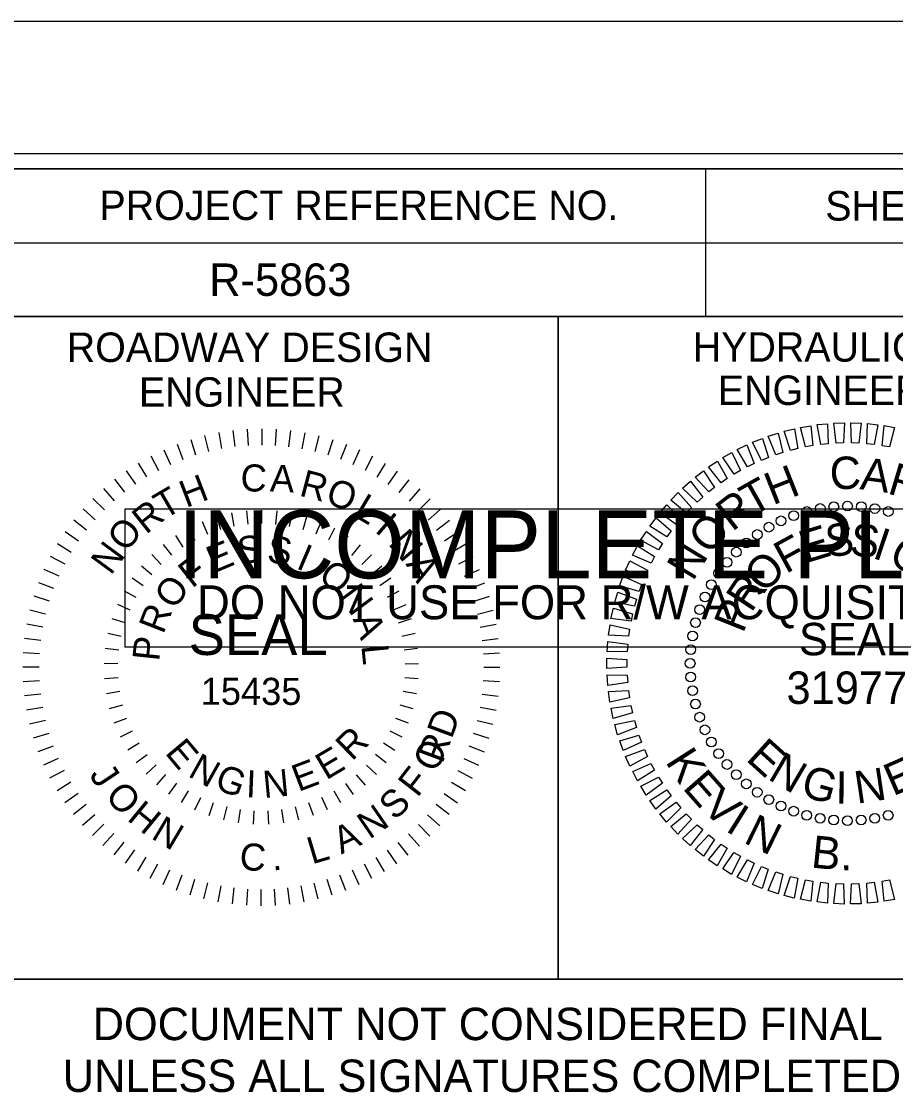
# Model space of a CAD drawing. Extents: x 557032 to 562069, y 513430 to 515874.
# Drawn here: x 558508.4 to 558656.7, y 515691.5 to 515874.3 of the extents above; entities that cross this region are included whole.
import ezdxf

# ---------------------------------------------------------------- set-up
doc = ezdxf.new("R2010")
doc.units = 0
for name, color, linetype in [('Default', 7, 'Continuous'), ('Old_Level_21', 7, 'Continuous'), ('Sheet Cutting Line CELL', 7, 'Continuous'), ('Sheet Data Field CELL', 7, 'Continuous'), ('Sheet Plot Border Inside CELL', 7, 'Continuous'), ('Sheet Plot Border Outside CELL', 7, 'Continuous'), ('Sheet Profile CELL', 7, 'Continuous'), ('Sheet Profile Grid Major CELL', 7, 'Continuous'), ('Sheet Sticker Exception Certification CELL', 7, 'Continuous'), ('Sheet Sticker Incomplete CELL', 7, 'Continuous')]:
    doc.layers.add(name, color=color, linetype=linetype)

msp = doc.modelspace()

# ---------------------------------------------------------------- linework, layer by layer
at = {"layer": 'Default'}
for points in [[(558644.01, 515802.48), (558643.39, 515805.86), (558645.17, 515806.01), (558645.26, 515802.62)], [(558646.61, 515802.7), (558646.23, 515806.12), (558648.01, 515806.15), (558647.87, 515802.76)], [(558649.23, 515802.75), (558649.08, 515806.18), (558650.86, 515806.09), (558650.48, 515802.71)], [(558651.83, 515802.61), (558651.93, 515806.04), (558653.7, 515805.82), (558653.08, 515802.49)], [(558636.39, 515800.73), (558635.08, 515803.9), (558636.78, 515804.42), (558637.58, 515801.12)], [(558638.89, 515801.49), (558637.8, 515804.75), (558639.54, 515805.15), (558640.1, 515801.8)], [(558641.43, 515802.07), (558640.58, 515805.4), (558642.34, 515805.68), (558642.67, 515802.3)], [(558654.43, 515802.29), (558654.76, 515805.71), (558656.51, 515805.37), (558655.67, 515802.08)], [(558631.58, 515798.69), (558629.84, 515801.66), (558631.46, 515802.41), (558632.71, 515799.25)], [(558633.95, 515799.79), (558632.42, 515802.87), (558634.09, 515803.51), (558635.11, 515800.27)], [(558629.29, 515797.43), (558627.36, 515800.26), (558628.91, 515801.12), (558630.38, 515798.06)], [(558627.1, 515796.01), (558624.97, 515798.7), (558626.46, 515799.67), (558628.14, 515796.72)], [(558625.02, 515794.44), (558622.7, 515796.97), (558624.12, 515798.04), (558626, 515795.22)], [(558623.04, 515792.72), (558620.56, 515795.1), (558621.9, 515796.26), (558623.97, 515793.57)], [(558621.19, 515790.88), (558618.55, 515793.07), (558619.81, 515794.33), (558622.06, 515791.79)], [(558619.48, 515788.91), (558616.69, 515790.91), (558617.86, 515792.25), (558620.28, 515789.88)], [(558617.91, 515786.82), (558614.98, 515788.63), (558616.05, 515790.05), (558618.64, 515787.85)], [(558616.48, 515784.64), (558613.44, 515786.23), (558614.41, 515787.72), (558617.14, 515785.71)], [(558615.21, 515782.35), (558612.07, 515783.73), (558612.93, 515785.29), (558615.8, 515783.47)], [(558614.11, 515779.99), (558610.87, 515781.14), (558611.62, 515782.75), (558614.61, 515781.14)], [(558613.17, 515777.55), (558609.86, 515778.48), (558610.5, 515780.14), (558613.59, 515778.73)], [(558612.4, 515775.05), (558609.04, 515775.75), (558609.56, 515777.45), (558612.74, 515776.26)], [(558611.81, 515772.51), (558608.41, 515772.96), (558608.81, 515774.7), (558612.07, 515773.74)], [(558611.4, 515769.93), (558607.97, 515770.15), (558608.25, 515771.9), (558611.57, 515771.17)], [(558611.17, 515767.33), (558607.74, 515767.31), (558607.89, 515769.08), (558611.25, 515768.58)], [(558611.12, 515764.71), (558607.7, 515764.45), (558607.73, 515766.23), (558611.12, 515765.97)], [(558611.26, 515762.11), (558607.86, 515761.61), (558607.77, 515763.38), (558611.16, 515763.36)], [(558611.58, 515759.51), (558608.22, 515758.78), (558608, 515760.55), (558611.39, 515760.76)], [(558612.07, 515756.95), (558608.77, 515755.98), (558608.44, 515757.73), (558611.8, 515758.18)], [(558612.75, 515754.43), (558609.52, 515753.23), (558609.06, 515754.95), (558612.39, 515755.63)], [(558613.59, 515751.96), (558610.46, 515750.54), (558609.89, 515752.22), (558613.16, 515753.13)], [(558614.61, 515749.55), (558611.59, 515747.92), (558610.89, 515749.56), (558614.09, 515750.7)], [(558615.8, 515747.22), (558612.89, 515745.38), (558612.09, 515746.97), (558615.2, 515748.33)], [(558617.14, 515744.98), (558614.37, 515742.95), (558613.46, 515744.47), (558616.47, 515746.04)], [(558618.64, 515742.84), (558616.02, 515740.62), (558615, 515742.08), (558617.89, 515743.85)], [(558620.28, 515740.81), (558617.82, 515738.41), (558616.7, 515739.79), (558619.46, 515741.77)], [(558622.06, 515738.9), (558619.77, 515736.33), (558618.56, 515737.63), (558621.18, 515739.8)], [(558623.97, 515737.12), (558621.87, 515734.4), (558620.57, 515735.61), (558623.03, 515737.95)], [(558625.99, 515735.47), (558624.09, 515732.61), (558622.71, 515733.73), (558625, 515736.24)], [(558628.13, 515733.97), (558626.43, 515730.98), (558624.97, 515732.01), (558627.08, 515734.67)], [(558630.37, 515732.62), (558628.88, 515729.53), (558627.36, 515730.44), (558629.28, 515733.24)], [(558632.7, 515731.43), (558631.43, 515728.24), (558629.84, 515729.05), (558631.56, 515731.98)], [(558635.1, 515730.41), (558634.06, 515727.14), (558632.42, 515727.83), (558633.93, 515730.88)], [(558637.57, 515729.56), (558636.76, 515726.22), (558635.07, 515726.8), (558636.37, 515729.94)], [(558640.09, 515728.88), (558639.51, 515725.49), (558637.79, 515725.96), (558638.87, 515729.18)], [(558642.65, 515728.38), (558642.31, 515724.96), (558640.57, 515725.3), (558641.41, 515728.59)], [(558645.25, 515728.06), (558645.15, 515724.63), (558643.38, 515724.84), (558643.99, 515728.18)], [(558647.85, 515727.92), (558647.99, 515724.49), (558646.22, 515724.58), (558646.6, 515727.96)], [(558650.46, 515727.96), (558650.84, 515724.55), (558649.07, 515724.52), (558649.21, 515727.91)], [(558653.07, 515728.19), (558653.68, 515724.81), (558651.91, 515724.66), (558651.82, 515728.05)], [(558655.65, 515728.6), (558656.5, 515725.27), (558654.74, 515724.99), (558654.41, 515728.37)]]:
    msp.add_lwpolyline(points, close=True, dxfattribs=at)
for centre in [(558639.41, 515790.42), (558641.63, 515791.12), (558643.91, 515791.63), (558646.22, 515791.93), (558648.54, 515792.03), (558650.87, 515791.93), (558653.18, 515791.62), (558655.45, 515791.12), (558635.2, 515788.46), (558637.26, 515789.53), (558633.23, 515787.21), (558631.38, 515785.79), (558629.67, 515784.22), (558628.09, 515782.5), (558626.67, 515780.65), (558625.42, 515778.69), (558624.35, 515776.62), (558623.45, 515774.47), (558622.75, 515772.25), (558622.25, 515769.98), (558621.95, 515767.67), (558621.84, 515765.34), (558621.94, 515763.01), (558622.25, 515760.7), (558622.75, 515758.43), (558623.45, 515756.21), (558624.34, 515754.06), (558625.42, 515751.99), (558626.67, 515750.03), (558628.09, 515748.18), (558629.66, 515746.46), (558631.38, 515744.89), (558633.22, 515743.47), (558635.19, 515742.22), (558637.25, 515741.14), (558639.4, 515740.25), (558641.62, 515739.55), (558655.44, 515739.55), (558643.9, 515739.04), (558646.21, 515738.74), (558648.53, 515738.64), (558650.86, 515738.74), (558653.17, 515739.04)]:
    msp.add_circle(centre, 0.826, dxfattribs=at)
at = {"layer": 'Old_Level_21'}
for p, q in [((558539.47, 515804), (558540.12, 515801.32)), ((558541.86, 515804.51), (558542.35, 515801.79)), ((558544.28, 515804.87), (558544.6, 515802.13)), ((558546.71, 515805.09), (558546.87, 515802.33)), ((558549.16, 515805.16), (558549.15, 515802.4)), ((558551.6, 515805.08), (558551.43, 515802.33)), ((558554.04, 515804.86), (558553.7, 515802.12)), ((558556.45, 515804.49), (558555.95, 515801.77)), ((558558.84, 515803.97), (558558.18, 515801.29)), ((558534.8, 515802.55), (558535.78, 515799.97)), ((558537.11, 515803.35), (558537.93, 515800.71)), ((558561.2, 515803.31), (558560.38, 515800.67)), ((558563.51, 515802.51), (558562.52, 515799.93)), ((558530.34, 515800.55), (558531.62, 515798.1)), ((558532.54, 515801.61), (558533.67, 515799.1)), ((558565.76, 515801.57), (558564.63, 515799.06)), ((558567.96, 515800.5), (558566.68, 515798.05)), ((558528.21, 515799.35), (558529.63, 515796.99)), ((558570.09, 515799.29), (558568.66, 515796.93)), ((558524.18, 515796.58), (558525.88, 515794.41)), ((558526.15, 515798.03), (558527.72, 515795.75)), ((558572.14, 515797.96), (558570.57, 515795.69)), ((558522.3, 515795.02), (558524.13, 515792.95)), ((558574.11, 515796.51), (558572.41, 515794.34)), ((558575.99, 515794.94), (558574.15, 515792.88)), ((558520.52, 515793.34), (558522.47, 515791.39)), ((558577.76, 515793.26), (558575.81, 515791.32)), ((558518.84, 515791.57), (558520.9, 515789.73)), ((558546.56, 515791.24), (558546.78, 515788.95)), ((558549.14, 515791.36), (558549.14, 515789.06)), ((558549.14, 515789.06), (558549.14, 515791.36)), ((558551.72, 515791.23), (558551.49, 515788.94)), ((558579.44, 515791.48), (558577.37, 515789.65)), ((558517.27, 515789.69), (558519.44, 515787.99)), ((558539.07, 515789.41), (558539.94, 515787.27)), ((558541.51, 515790.26), (558542.16, 515788.05)), ((558544.01, 515790.87), (558544.45, 515788.61)), ((558554.26, 515790.85), (558553.82, 515788.6)), ((558556.76, 515790.24), (558556.11, 515788.03)), ((558559.2, 515789.38), (558558.33, 515787.25)), ((558581, 515789.6), (558578.83, 515787.9)), ((558515.82, 515787.72), (558518.09, 515786.15)), ((558536.74, 515788.32), (558537.8, 515786.28)), ((558561.53, 515788.29), (558560.46, 515786.25)), ((558582.45, 515787.63), (558580.18, 515786.06)), ((558514.49, 515785.67), (558516.85, 515784.24)), ((558534.51, 515787.02), (558535.77, 515785.09)), ((558563.75, 515786.98), (558562.49, 515785.05)), ((558530.49, 515783.8), (558532.1, 515782.15)), ((558532.42, 515785.5), (558533.86, 515783.71)), ((558565.84, 515785.46), (558564.39, 515783.66)), ((558583.77, 515785.58), (558581.41, 515784.15)), ((558513.28, 515783.54), (558515.73, 515782.26)), ((558567.76, 515783.75), (558566.15, 515782.1)), ((558584.97, 515783.44), (558582.53, 515782.16)), ((558512.21, 515781.34), (558514.73, 515780.21)), ((558528.74, 515781.91), (558530.49, 515780.43)), ((558569.52, 515781.86), (558567.76, 515780.38)), ((558586.04, 515781.24), (558583.52, 515780.11)), ((558511.27, 515779.09), (558513.85, 515778.1)), ((558527.16, 515779.87), (558529.06, 515778.55)), ((558571.08, 515779.81), (558569.19, 515778.5)), ((558586.97, 515778.98), (558584.39, 515778)), ((558510.47, 515776.78), (558513.11, 515775.95)), ((558525.81, 515777.68), (558527.81, 515776.56)), ((558572.43, 515777.62), (558570.43, 515776.5)), ((558587.77, 515776.67), (558585.13, 515775.85)), ((558524.66, 515775.37), (558526.76, 515774.45)), ((558573.58, 515775.3), (558571.47, 515774.39)), ((558509.81, 515774.42), (558512.49, 515773.76)), ((558523.74, 515772.96), (558525.93, 515772.25)), ((558574.49, 515772.89), (558572.3, 515772.18)), ((558588.42, 515774.31), (558585.74, 515773.66)), ((558509.29, 515772.03), (558512.01, 515771.53)), ((558588.93, 515771.92), (558586.22, 515771.43)), ((558508.93, 515769.62), (558511.66, 515769.28)), ((558523.06, 515770.47), (558525.3, 515769.97)), ((558575.16, 515770.4), (558572.91, 515769.91)), ((558589.29, 515769.5), (558586.55, 515769.18)), ((558522.62, 515767.93), (558524.9, 515767.66)), ((558575.59, 515767.86), (558573.31, 515767.59)), ((558508.7, 515767.18), (558511.45, 515767.01)), ((558589.51, 515767.07), (558586.76, 515766.91)), ((558508.62, 515764.74), (558511.38, 515764.73)), ((558522.43, 515765.36), (558524.73, 515765.3)), ((558575.78, 515765.29), (558573.48, 515765.23)), ((558589.58, 515764.62), (558586.82, 515764.63)), ((558508.69, 515762.29), (558511.45, 515762.45)), ((558522.49, 515762.78), (558524.78, 515762.95)), ((558575.71, 515762.71), (558573.42, 515762.88)), ((558589.5, 515762.18), (558586.75, 515762.35)), ((558508.91, 515759.86), (558511.65, 515760.18)), ((558522.8, 515760.23), (558525.06, 515760.61)), ((558573.14, 515760.62), (558575.41, 515760.24)), ((558589.28, 515759.74), (558586.54, 515760.08)), ((558523.35, 515757.7), (558525.57, 515758.31)), ((558574.84, 515757.63), (558572.62, 515758.24)), ((558509.27, 515757.44), (558511.99, 515757.93)), ((558588.91, 515757.33), (558586.2, 515757.83)), ((558509.78, 515755.05), (558512.46, 515755.7)), ((558524.14, 515755.25), (558526.29, 515756.06)), ((558574.03, 515755.18), (558571.89, 515756)), ((558588.39, 515754.94), (558585.71, 515755.6)), ((558510.44, 515752.69), (558513.08, 515753.51)), ((558525.17, 515752.89), (558527.23, 515753.91)), ((558573, 515752.82), (558570.94, 515753.85)), ((558587.73, 515752.58), (558585.1, 515753.41)), ((558511.23, 515750.38), (558513.81, 515751.36)), ((558526.42, 515750.64), (558528.37, 515751.84)), ((558571.75, 515750.57), (558569.79, 515751.79)), ((558586.93, 515750.27), (558584.35, 515751.26)), ((558512.17, 515748.12), (558514.68, 515749.25)), ((558527.88, 515748.51), (558529.71, 515749.9)), ((558570.28, 515748.45), (558568.45, 515749.85)), ((558585.99, 515748.02), (558583.48, 515749.15)), ((558529.54, 515746.54), (558531.22, 515748.1)), ((558568.61, 515746.49), (558566.93, 515748.05)), ((558513.23, 515745.92), (558515.68, 515747.2)), ((558531.38, 515744.74), (558532.91, 515746.46)), ((558566.77, 515744.69), (558565.24, 515746.41)), ((558584.92, 515745.82), (558582.48, 515747.1)), ((558514.43, 515743.79), (558516.79, 515745.21)), ((558533.39, 515743.12), (558534.74, 515744.98)), ((558535.54, 515741.7), (558536.71, 515743.69)), ((558562.6, 515741.67), (558561.43, 515743.65)), ((558564.75, 515743.08), (558563.41, 515744.94)), ((558583.71, 515743.69), (558581.36, 515745.12)), ((558515.76, 515741.73), (558518.03, 515743.3)), ((558537.83, 515740.5), (558538.8, 515742.59)), ((558560.31, 515740.47), (558559.34, 515742.56)), ((558582.38, 515741.64), (558580.12, 515743.21)), ((558517.2, 515739.76), (558519.38, 515741.46)), ((558540.21, 515739.53), (558540.98, 515741.7)), ((558543.22, 515741.02), (558542.66, 515738.79)), ((558545.21, 515738.29), (558545.55, 515740.56)), ((558547.78, 515738.03), (558547.89, 515740.33)), ((558550.35, 515738.03), (558550.25, 515740.33)), ((558552.92, 515738.28), (558552.59, 515740.55)), ((558555.45, 515738.77), (558554.9, 515741)), ((558557.92, 515739.5), (558557.16, 515741.67)), ((558580.93, 515739.67), (558578.76, 515741.38)), ((558518.77, 515737.88), (558520.83, 515739.71)), ((558579.36, 515737.79), (558577.3, 515739.63)), ((558520.44, 515736.1), (558522.39, 515738.04)), ((558522.22, 515734.42), (558524.05, 515736.48)), ((558575.9, 515734.34), (558574.08, 515736.41)), ((558577.68, 515736.02), (558575.74, 515737.97)), ((558524.1, 515732.85), (558525.8, 515735.02)), ((558574.02, 515732.78), (558572.32, 515734.95)), ((558526.06, 515731.4), (558527.63, 515733.67)), ((558572.05, 515731.33), (558570.49, 515733.61)), ((558528.11, 515730.07), (558529.54, 515732.43)), ((558530.24, 515728.86), (558531.53, 515731.31)), ((558567.86, 515728.81), (558566.58, 515731.26)), ((558570, 515730.01), (558568.57, 515732.37)), ((558532.44, 515727.79), (558533.57, 515730.31)), ((558534.7, 515726.85), (558535.68, 515729.43)), ((558563.4, 515726.81), (558562.43, 515729.39)), ((558565.66, 515727.75), (558564.54, 515730.26)), ((558537, 515726.05), (558537.83, 515728.69)), ((558539.36, 515725.39), (558540.02, 515728.07)), ((558541.75, 515724.87), (558542.25, 515727.59)), ((558544.17, 515724.5), (558544.5, 515727.24)), ((558553.93, 515724.49), (558553.6, 515727.23)), ((558556.34, 515724.85), (558555.85, 515727.57)), ((558558.73, 515725.36), (558558.08, 515728.04)), ((558561.09, 515726.01), (558560.28, 515728.65)), ((558546.6, 515724.28), (558546.77, 515727.03)), ((558549.05, 515724.2), (558549.05, 515726.96)), ((558551.49, 515724.27), (558551.33, 515727.03))]:
    msp.add_line(p, q, dxfattribs=at)
at = {"layer": 'Sheet Cutting Line CELL'}
msp.add_line((558716.45, 515874.28), (557032.45, 515874.28), dxfattribs=at)
at = {"layer": 'Sheet Plot Border Inside CELL'}
msp.add_lwpolyline([(557045.45, 514796.73), (558711.95, 514796.73), (558711.95, 515851.83), (557045.45, 515851.83)], close=True, dxfattribs=at)
at = {"layer": 'Sheet Plot Border Outside CELL'}
msp.add_lwpolyline([(557032.45, 514774.28), (558716.45, 514774.28), (558716.45, 515874.28), (557032.45, 515874.28)], close=True, dxfattribs=at)
at = {"layer": 'Sheet Profile CELL'}
for p, q in [((558624.45, 515849.23), (558624.45, 515824.23)), ((558499.4, 515836.73), (558699.45, 515836.73)), ((558599.45, 515824.23), (558599.45, 515711.78))]:
    msp.add_line(p, q, dxfattribs=at)
for points in [[(558699.45, 515849.28), (557199.45, 515849.28), (557199.45, 514799.28), (558699.45, 514799.28)], [(558499.4, 515849.28), (558699.45, 515849.28), (558699.45, 515824.23), (558499.4, 515824.23)], [(558499.4, 515824.23), (558599.45, 515824.23), (558599.45, 515711.73), (558499.4, 515711.73)], [(558599.45, 515824.23), (558699.45, 515824.23), (558699.45, 515711.73), (558599.45, 515711.73)]]:
    msp.add_lwpolyline(points, close=True, dxfattribs=at)
at = {"layer": 'Sheet Profile Grid Major CELL'}
msp.add_lwpolyline([(558149.45, 515349.28), (558199.45, 515349.28), (558199.45, 515849.28), (558249.45, 515849.28), (558249.45, 515349.28), (558299.45, 515349.28), (558299.45, 515849.28), (558349.45, 515849.28), (558349.45, 515349.28), (558399.45, 515349.28), (558399.45, 515849.28), (558449.45, 515849.28), (558449.45, 515349.28), (558499.45, 515349.28), (558499.45, 515849.28), (558525.75, 515849.28)], dxfattribs=at)
at = {"layer": 'Sheet Sticker Exception Certification CELL'}
msp.add_line((558499.4, 515711.73), (558699.44, 515711.73), dxfattribs=at)
msp.add_line((558499.4, 515711.73), (558699.44, 515711.73), dxfattribs=at)
at = {"layer": 'Sheet Sticker Incomplete CELL'}
msp.add_lwpolyline([(558525.97, 515768.08), (558525.97, 515791.58), (558672.97, 515791.58), (558672.97, 515768.08)], close=True, dxfattribs=at)

# ---------------------------------------------------------------- texts
at = {"layer": 'Default'}
for s, height, rotation, p in [('C', 5.5, 1.9509, (558645.61, 515794.84)), ('H', 5.5, 21.5901, (558635.86, 515792.14)), ('A', 5.5, 352.4458, (558650.52, 515794.92)), ('R', 5.5, 343.3983, (558655.15, 515794.24)), ('T', 5.5, 29.3793, (558632.35, 515790.17)), ('R', 5.5, 37.5879, (558628.97, 515787.6)), ('O', 5.5, 48.3131, (558625.16, 515783.57)), ('E', 5.5, 16.975, (558641.35, 515782.28)), ('S', 5.5, 5.2127, (558644.96, 515783.39)), ('S', 5.5, 353.2538, (558648.78, 515783.74)), ('I', 5.5, 341.2948, (558652.58, 515783.29)), ('N', 5.5, 58.5235, (558622.3, 515779.14)), ('F', 5.5, 28.6529, (558638.07, 515780.47)), ('O', 5.5, 332.5394, (558655.27, 515782.46)), ('O', 5.5, 44.4617, (558634.34, 515777.05)), ('R', 5.5, 56.5612, (558632.21, 515773.81)), ('P', 5.5, 68.3234, (558630.82, 515770.3)), ('SEAL', 5.504, 359.989, (558640.31, 515766.71)), ('31977', 5.504, 359.989, (558638.19, 515758.46)), ('K', 5.5, 302.6028, (558617.54, 515748.67)), ('E', 5.5, 317.8396, (558631.13, 515748.98)), ('N', 5.5, 329.6019, (558634.83, 515745.78)), ('E', 5.5, 23.5075, (558656.27, 515742.74)), ('E', 5.5, 311.3071, (558620.42, 515744.17)), ('G', 5.5, 344.6519, (558640.38, 515742.89)), ('N', 5.5, 8.4574, (558650.13, 515741.5)), ('I', 5.5, 359.702, (558646.49, 515741.54)), ('V', 5.5, 319.287, (558623.63, 515740.48)), ('I', 5.5, 327.9723, (558627.67, 515737)), ('N', 5.5, 333.9122, (558630.71, 515734.99)), ('B', 5.5, 354.009, (558642.23, 515730.71)), ('.', 5.5, 2.3511, (558647.32, 515730.16))]:
    msp.add_text(s, height=height, rotation=rotation, dxfattribs=at).set_placement(p)
at = {"layer": 'Old_Level_21'}
for s, height, rotation, p in [('C', 4.59, 357.2771, (558545.47, 515794.63)), ('A', 4.59, 357.2771, (558550.49, 515794.53)), ('H', 4.59, 20.9878, (558536.32, 515791.69)), ('R', 4.59, 345.2678, (558555.36, 515793.85)), ('T', 4.59, 30.4198, (558532.62, 515789.69)), ('O', 4.59, 342.211, (558559.81, 515792.52)), ('L', 4.59, 329.0747, (558564.48, 515790.46)), ('R', 4.59, 38.5807, (558529.52, 515787.13)), ('O', 4.59, 51.6375, (558526.19, 515784.04)), ('I', 4.59, 319.4993, (558568.18, 515787.79)), ('N', 4.59, 310.2048, (558570.48, 515785.62)), ('N', 4.59, 53.5969, (558523.55, 515780.16)), ('E', 4.59, 22.8645, (558541.02, 515780.58)), ('S', 4.59, 7.5683, (558545.34, 515782.16)), ('S', 4.59, 352.272, (558549.92, 515782.53)), ('I', 4.59, 336.9758, (558554.81, 515781.53)), ('F', 4.59, 38.1608, (558537.34, 515777.99)), ('O', 4.59, 321.6795, (558558.51, 515779.74)), ('A', 4.59, 300.4373, (558573.51, 515782.23)), ('O', 4.59, 53.457, (558534.28, 515774.29)), ('N', 4.59, 306.3833, (558562.05, 515776.66)), ('R', 4.59, 68.7533, (558532.45, 515770.16)), ('SEAL', 6.898, 359.9202, (558536.75, 515766.77)), ('A', 4.59, 291.0871, (558564.56, 515772.89)), ('P', 4.59, 84.0495, (558531.75, 515765.61)), ('L', 4.59, 275.7908, (558566.04, 515768.34)), ('15435', 4.595, 359.9202, (558538.8, 515758.31)), (' RD', 4.595, 69.5926, (558579.23, 515746.62)), ('R', 4.59, 44.4851, (558564.47, 515748.65)), ('E', 4.59, 309.9903, (558532.61, 515750.11)), ('E', 4.59, 30.714, (558560.09, 515745.45)), ('O ', 4.595, 60.9198, (558578.56, 515746.6)), ('N', 4.59, 330.8453, (558536.47, 515746.27)), ('E', 4.59, 20.7281, (558555.37, 515743.49)), ('J', 4.59, 303.8552, (558519.79, 515746.37)), ('G', 4.59, 339.6116, (558540.96, 515744.11)), ('N', 4.59, 5.336, (558549.55, 515742.48)), ('F', 4.59, 52.1272, (558575.56, 515742.45)), ('I', 4.59, 357.7064, (558546.43, 515742.63)), ('O', 4.59, 311.927, (558522.41, 515742.71)), ('S', 4.59, 43.2446, (558571.73, 515738.56)), ('H', 4.59, 320.5697, (558526.15, 515738.83)), ('N', 4.59, 34.362, (558567.43, 515735.38)), ('N', 4.59, 329.2423, (558530.22, 515735.72)), ('A', 4.59, 25.5393, (558562.65, 515732.88)), ('C', 4.59, 356.0101, (558545.29, 515730.33)), ('L', 4.59, 16.5368, (558557.68, 515731.2)), ('.', 4.59, 3.7525, (558551, 515730.19))]:
    msp.add_text(s, height=height, rotation=rotation, dxfattribs=at).set_placement(p)
at = {"layer": 'Sheet Data Field CELL'}
msp.add_text('R-5863   ', height=5.5, dxfattribs=at).set_placement((558540.25, 515827.72))
at = {"layer": 'Sheet Profile CELL'}
for s, height, p in [('PROJECT REFERENCE NO.', 5.0001, (558521.62, 515840.6)), ('SHEET NO.', 5, (558644.77, 515840.5)), ('ROADWAY DESIGN', 5.0001, (558516.07, 515816.5)), ('HYDRAULICS', 5, (558622.27, 515816.55)), ('ENGINEER', 5, (558528.32, 515808.9)), ('ENGINEER', 5, (558626.52, 515809.2))]:
    msp.add_text(s, height=height, dxfattribs=at).set_placement(p)
at = {"layer": 'Sheet Sticker Exception Certification CELL'}
for s, p in [('DOCUMENT NOT CONSIDERED FINAL', (558520.47, 515701.39)), ('DOCUMENT NOT CONSIDERED FINAL', (558520.47, 515701.39)), ('UNLESS ALL SIGNATURES COMPLETED', (558515.4, 515692.59)), ('UNLESS ALL SIGNATURES COMPLETED', (558515.4, 515692.59))]:
    msp.add_text(s, height=5.5, dxfattribs=at).set_placement(p)
at = {"layer": 'Sheet Sticker Incomplete CELL'}
for s, height, p in [('INCOMPLETE PLANS', 11.52, (558534.93, 515779.78)), ('DO NOT USE FOR R/W ACQUISITION', 5.76, (558538.18, 515772.83))]:
    msp.add_text(s, height=height, dxfattribs=at).set_placement(p)

doc.saveas('drawing.dxf')
